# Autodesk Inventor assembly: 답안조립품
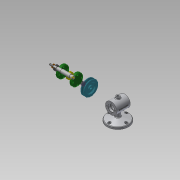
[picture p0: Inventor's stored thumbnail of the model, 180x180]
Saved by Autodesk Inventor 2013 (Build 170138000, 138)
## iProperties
Created: 2018-12
Part Number: 답안조립품
Document SubType Name: Assembly
Designer: Administrator
Author: Administrator
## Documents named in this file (15)
- C:\Users\Administrator\Desktop\481207V1062\답안조립품.iam
- C:\Users\Administrator\Desktop\481207V1062\본체.ipt
- C:\Users\Administrator\Desktop\481207V1062\V벨트풀리.ipt
- C:\Users\Administrator\Desktop\481207V1062\고무캡.ipt
- C:\Users\Administrator\Desktop\481207V1062\너트 M8.ipt
- 너트 M8.ipt
- C:\Users\Administrator\Desktop\481207V1062\뒤커버.ipt
- C:\Users\Administrator\Desktop\481207V1062\베어링 15 x 32 x 9.ipt
- C:\Users\Administrator\Desktop\481207V1062\볼트 M4 x 12.ipt
- C:\Users\Administrator\Desktop\481207V1062\스프링와셔 8.ipt
- C:\Users\Administrator\Desktop\481207V1062\앞커버.ipt
- C:\Users\Administrator\Desktop\481207V1062\오일 실 15 25 7.ipt
- C:\Users\Administrator\Desktop\481207V1062\와셔 8x17.ipt
- C:\Users\Administrator\Desktop\481207V1062\축.ipt
- C:\Users\Administrator\Desktop\481207V1062\키 3 x 3 x 12.ipt
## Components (2 placed, 2 different names)
1. V벨트풀리:1
2. 고무캡:1
